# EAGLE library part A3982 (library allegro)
DMOS Stepper Motor Driver with Translator Auto generated by make-symbol-device-package-bsdl.ulp Rev. 32 Source: http://www.allegromicro.com/en/Products/Part_Numbers/3982/3982.pdf
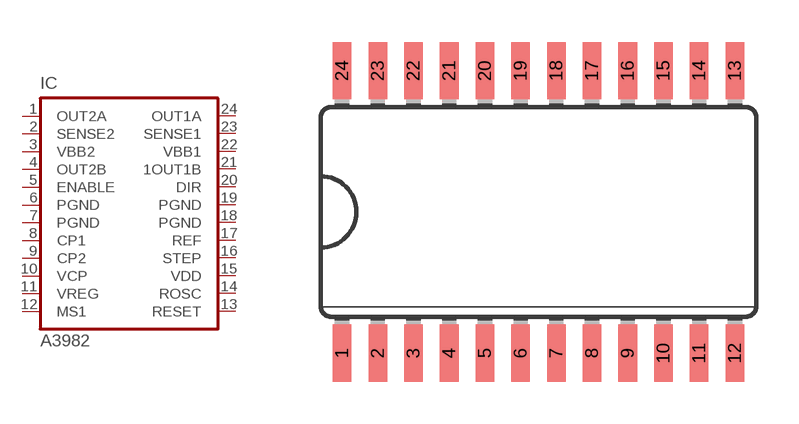
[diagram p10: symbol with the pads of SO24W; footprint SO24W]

Designator prefix IC

## A3982 (MF: ALLEGRO MICROSYSTEMS, INC.; MPN: A3982SLB-T; OC_FARNELL: 1521717; OC_NEWARK: 59J2492)  [SO24W]
1  OUT2A  out
2  SENSE2  in
3  VBB2  pwr
4  OUT2B  out
5  ENABLE  in
6  PGND  pwr
7  PGND  pwr
8  CP1  pas
9  CP2  pas
10  VCP  pas
11  VREG  pas
12  MS1  in
13  RESET  in
14  ROSC  in
15  VDD  pwr
16  STEP  in
17  REF  in
18  PGND  pwr
19  PGND  pwr
20  DIR  in
21  1OUT1B  out
22  VBB1  pwr
23  SENSE1  in
24  OUT1A  out

## Footprint SO24W (pad centres in mm)
Small Outline Package 24 wide
smd 0.66 x 2.032: 1 -6.985,-5.029; 2 -5.715,-5.029; 3 -4.445,-5.029; 4 -3.175,-5.029; 5 -1.905,-5.029; 6 -0.635,-5.029; 7 0.635,-5.029; 8 1.905,-5.029; 9 3.175,-5.029; 10 4.445,-5.029; 11 5.715,-5.029; 12 6.985,-5.029; 13 6.985,5.029; 14 5.715,5.029; 15 4.445,5.029; 16 3.175,5.029; 17 1.905,5.029; 18 0.635,5.029; 19 -0.635,5.029; 20 -1.905,5.029; 21 -3.175,5.029; 22 -4.445,5.029; 23 -5.715,5.029; 24 -6.985,5.029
